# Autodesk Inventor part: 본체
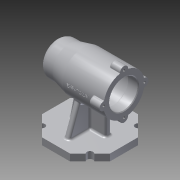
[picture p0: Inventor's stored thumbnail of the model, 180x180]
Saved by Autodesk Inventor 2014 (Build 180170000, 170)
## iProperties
Created: 2021-01
Part Number: 본체
Material: Aluminum 6061
Document SubType Name: Modeling
Designer: kh
Density: 2.71 g/cm^3
Appearance: Aluminum - Flat
Mass: 632.295 g
Surface Area: 613.777 cm^2
Volume: 233.319 cm^3
Author: kh
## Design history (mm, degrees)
sketch "Sketch1" dims "d0" = 100
  geometry: L1 (20.711, 50)-(50, 20.711); L2 (50, 20.711)-(50, -20.711); L3 (50, -20.711)-(20.711, -50); L4 (20.711, -50)-(-20.711, -50); L5 (-20.711, -50)-(-50, -20.711); L6 (-50, -20.711)-(-50, 20.711); L7 (-50, 20.711)-(-20.711, 50); L8 (-20.711, 50)-(20.711, 50); 4 further points
  constraints: 16 end point, 2 coincident, 1 horizontal, 1 midpoint, 1 vertical alignment, 19 other
extrude "Extrusion1" new body sketch "Sketch1" distance "d1" = 10; taper "d2" = 0 deg
sketch "Sketch2"
  geometry: L1 (50, 20.711)-(20.711, 50) reference; L2 (20.711, 50)-(-20.711, 50) reference; L3 (-20.711, 50)-(-50, 20.711) reference; L4 (-50, 20.711)-(-50, -20.711) reference; L5 (-50, -20.711)-(-20.711, -50) reference; L6 (-20.711, -50)-(20.711, -50) reference; L7 (20.711, -50)-(50, -20.711) reference; L8 (50, -20.711)-(50, 20.711) reference; L9 (-35.355, 35.355)-(35.355, -35.355); L10 (35.355, 35.355)-(-35.355, -35.355); C1 r 4.5 at (35.355, 35.355); C2 r 4.5 at (35.355, -35.355); C3 r 4.5 at (-35.355, -35.355); C4 r 4.5 at (-35.355, 35.355); 2 further points
  constraints: 5 midpoint, 4 centre point, 4 coincident, 4 end point, 2 perpendicular, 1 point on line
  dimensions: "d3" = 9 diameter of C1; "d4" = 9 diameter of C2; "d5" = 9 diameter of C3; "d6" = 9 diameter of C4
extrude "Extrusion2" cut sketch "Sketch2" stored distance "d7" = 0; taper "d8" = 0 deg
sketch "Sketch3"
  geometry: L1 (0, 0)-(0, 75); L2 (-50, 0)-(-50, 10) reference; L3 (-50, 75)-(50, 75); L4 (50, 75)-(50, 100); L5 (50, 100)-(30, 100); L6 (30, 100)-(10, 105); L7 (10, 105)-(-50, 105); L8 (-50, 105)-(-50, 75); L9 (-50, 96)-(-35, 96); L10 (-35, 96)-(-35, 75); L11 (-35, 75)-(-50, 75); L12 (-50, 75)-(-50, 96); L13 (-35, 75)-(7, 75); L14 (7, 75)-(7, 99); L15 (7, 99)-(-35, 99); L16 (-35, 99)-(-35, 75); L17 (7, 75)-(19, 75); L18 (19, 75)-(19, 96); L19 (19, 96)-(7, 96); L20 (7, 96)-(7, 75); L21 (19, 75)-(37, 75); L22 (37, 75)-(37, 92.5); L23 (37, 92.5)-(19, 92.5); L24 (19, 92.5)-(19, 75); L25 (37, 75)-(41, 75); L26 (41, 75)-(41, 91); L27 (41, 91)-(37, 91); L28 (37, 91)-(37, 75); L29 (41, 75)-(44, 75); L30 (44, 75)-(44, 85.5); L31 (44, 85.5)-(41, 85.5); L32 (41, 85.5)-(41, 75)
  constraints: 62 end point, 15 parallel, 8 perpendicular, 6 horizontal, 2 point on line, 1 collinear, 1 midpoint, 1 vertical
  dimensions: "d9" = 75 distance of L1.start L1.end; "d10" = 60 diameter of L7 L3; "d11" = 50 diameter of L5 L3; "d12" = 20 distance from line of L5.end L4; "d13" = 40 distance from line of L6.end L4; "d14" = 100 distance between parallel lines of L8 L4; "d15" = 15 distance between parallel lines of L8 L10; "d16" = 42 distance between parallel lines of L10 L20; "d17" = 12 distance between parallel lines of L20 L24; "d18" = 18 distance between parallel lines of L24 L22; "d19" = 4 distance of L26.end L27.end; "d20" = 3 distance of L30.end L31.end; "d21" = 21 diameter of L31 L3; "d22" = 32 diameter of L27 L3; "d23" = 35 diameter of L23 L3; "d24" = 48 diameter of L15 L13; "d25" = 42 diameter of L19 L17; "d26" = 42 diameter of L9 L3
revolve "Revolution1" sketch "Sketch3" stored, may be unused: angle "d27" = 90 deg
sketch "Sketch4"
  geometry: L1 (-30, 0)-(30, 0); L2 (0, 30)-(0, -30); C1 r 6 at (-30, 0); C2 r 6 at (0, 30); C3 r 6 at (30, 0); C4 r 6 at (0, -30); A1 r 30 centre (0, 0) between (0, -30) and (-30, 0) reference; 2 further points
  constraints: 5 coincident, 4 centre point, 4 end point, 2 midpoint, 2 point on circle, 1 horizontal, 1 perpendicular
  dimensions: "d28" = 12 diameter of C1; "d29" = 12 diameter of C2 (= d28); "d30" = 12 diameter of C3 (= d28); "d31" = 12 diameter of C4 (= d28)
extrude "Extrusion3" join sketch "Sketch4" distance "d32" = 16; taper "d33" = 0 deg
sketch "Sketch5"
  geometry: L1 (20.711, 0)-(-20.711, 0) reference; L2 (-27, 0)-(-27, 51); L3 (-50, 0)-(-50, 10) reference; L4 (27, 10)-(19.03, 51); L5 (38.537, 10)-(50, 10) reference; L6 (20.711, 10)-(32.173, 10) reference; L7 (50, 0)-(50, 10) reference; L8 (27, 10)-(-27, 10); L9 (19.03, 51)-(-27, 51); L10 (-35, 51)-(7, 51) reference; 1 further point
  constraints: 8 end point, 4 point on line, 2 perpendicular, 1 parallel
  dimensions: "d34" = 23 distance between parallel lines of L3 L2; "d35" = 101 deg angle of L5 L4; "d36" = 23 distance from line of L4.start L7
extrude "Extrusion4" join sketch "Sketch5" stored distance "d37" = 8; taper "d38" = 0 deg
sketch "Sketch6"
  geometry: L1 (-35, 10)-(-23.246, 42.294); L2 (23.02, 42.915)-(35, 10); L3 (0, 0)-(0, 55.467); L4 (-38.537, 10)-(-30.855, 10) reference; L5 (-20.711, 10)-(-32.173, 10) reference; L6 (50, 10)-(38.537, 10) reference; L7 (30.855, 10)-(38.537, 10) reference; L8 (-50, 0)-(-50, 10) reference; 1 further point
  constraints: 6 end point, 2 point on line, 1 vertical, 1 other
  dimensions: "d39" = 15 distance from line of L8 L1.start; "d40" = 110 deg angle of L4 L1
feature "Rib1" dims "d41" = 1, "d42" = 8, "d43" = 0, "d44" = 0, "d45" = 1, "d46" = 1
feature "Rib2" dims "d47" = 1, "d48" = 8, "d49" = 0, "d50" = 0, "d51" = 1, "d52" = 1
sketch "Sketch7"
  geometry: L1 (0, 0)-(60, 0); L2 (30, 30)-(30, -30); A1 r 30 centre (30, 0) between (24.03, 29.4) and (0.6, 5.97) reference; A2 r 30 centre (30, 0) between (30, 30) and (0, 0); 7 further points
  constraints: 7 coincident, 4 end point, 2 midpoint, 2 point on circle, 1 centre point, 1 concentric, 1 horizontal, 1 perpendicular
hole "Hole1" sketch "Sketch7" at (0, 0), (30, -30), (60, 0), (30, 30) diameter "d53" = 3.242; stored, may be unused: countersink angle "d57" = 90 deg, drill point angle "d59" = 118 deg; dims "d54" = 8, "d55" = 4, "d56" = 2, "d58" = 10
fillet "Fillet1" dims "d60" = 0.3, "d61" = 3
fillet "Fillet2" dims "d62" = 1, "d63" = 10, "d64" = 3
fillet "Fillet3" dims "d65" = 3
fillet "Fillet4" dims "d66" = 3
workplane "Work Plane2"
  workplane "Work Plane1"
sketch "Sketch8"
  geometry: L1 (-24.592, 2.402)-(8.592, 2.402); L2 (8.592, 2.402)-(8.592, -2.402); L3 (8.592, -2.402)-(-24.592, -2.402); L4 (-24.592, -2.402)-(-24.592, 2.402); L5 (-24.592, 2.402)-(8.592, -2.402); L6 (30, 29.226)-(30, 6.771) reference; L7 (-70, -15)-(-70, 15) reference; L8 (-70, 0)-(30, 0); 2 further points
  constraints: 4 end point, 2 midpoint, 1 perpendicular, 1 point on line, 2 other
  dimensions: "d68" = 38 distance from line of L6 point (-8, 0)
emboss "Emboss1" sketch "Sketch8" dims "d0" = 100, "d69" = 0.5, "d70" = 0
chamfer "Chamfer1" distance "d71" = 1; stored, may be unused: second distance "d72" = 2, angle "d73" = 45 deg
body "Solid1"
node "Projected Loop1"
other parameters: "d67" = 0.5
